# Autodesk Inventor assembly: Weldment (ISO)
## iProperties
Length Units: 11269
Angle Units: 11283
Time Units: 11279
Mass Units: 11290
Length Display Precision: 3
Angle Display Precision: 2
Part Number: Weldment (ISO)
Document SubType Name: Weldment
Created: 2002-06
Designer: smithga
Part Number: Ens_pied_support
Created: 2008-03
Designer: Pascal
Material: Aluminum soudé-6061
Control State: 0
Master: False
Shininess: 64.0
Angle Units: 11279
Time Units: 11290
Mass Units: 11283
Compacted: True
DESIGNATION: Ensemble pied support
Density: 0.0
Volumn: 0.0
Area: 0.0
PropertySet Name: Model Information
Author: Pascal
